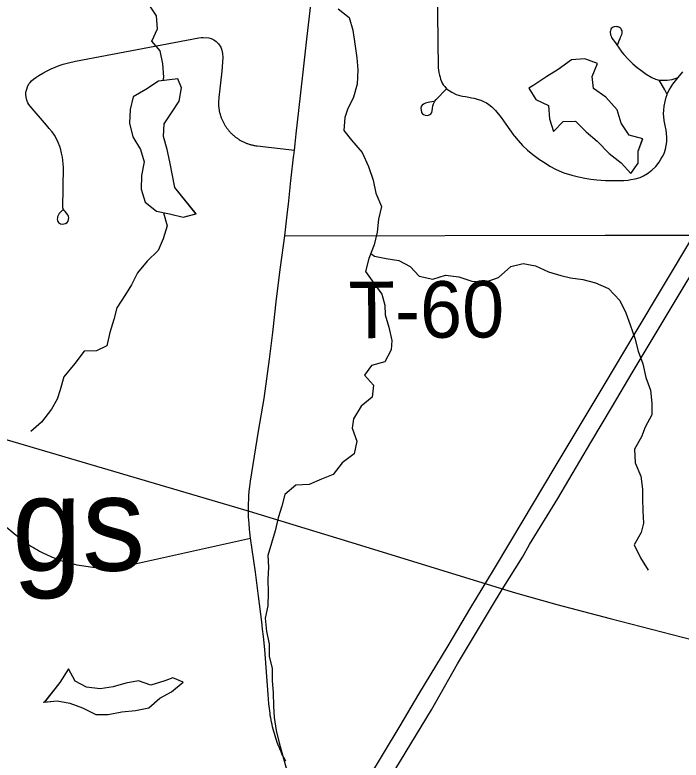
# Model space of a CAD drawing. Extents: x 0 to 34, y 0 to 22.
# Drawn here: x 5.8802 to 6.2147, y 14.8603 to 15.2346 of the extents above; entities that cross this region are included whole.
import ezdxf

# ---------------------------------------------------------------- set-up
doc = ezdxf.new("R2010")
doc.units = 0
for name, color, linetype in [('GM_X_County_Road', 7, 'Continuous'), ('GM_X_Interstate_Route', 7, 'Continuous'), ('GM_X_Major_River', 7, 'Continuous'), ('GM_X_Minor_Lake', 7, 'Continuous'), ('GM_X_Minor_Lake_Text', 7, 'Continuous'), ('GM_X_Minor_River', 7, 'Continuous'), ('GM_X_Rail_Line', 7, 'Continuous'), ('GM_X_Township_Road', 7, 'Continuous'), ('GM_X_Township_Road_Text', 7, 'Continuous')]:
    doc.layers.add(name, color=color, linetype=linetype)

msp = doc.modelspace()

# ---------------------------------------------------------------- linework, layer by layer
at = {"layer": 'GM_X_County_Road'}
for points in [[(6.01571, 15.1237), (6.01705, 15.13566), (6.01748, 15.13958), (6.01841, 15.14791), (6.01863, 15.14993), (6.01879, 15.1513), (6.01896, 15.15282), (6.0201, 15.16312), (6.02019, 15.16395), (6.0205, 15.16667), (6.02086, 15.16976), (6.02146, 15.17481), (6.02274, 15.18654), (6.0249, 15.20591), (6.02676, 15.22248), (6.02956, 15.24694)], [(6.01616, 14.85978), (6.01566, 14.86071), (6.01518, 14.86164), (6.01471, 14.86258), (6.01426, 14.86353), (6.01382, 14.86448), (6.0134, 14.86545), (6.013, 14.86642), (6.01262, 14.8674), (6.01225, 14.86838), (6.01194, 14.86917), (6.01154, 14.87028), (6.01116, 14.87138), (6.0108, 14.8725), (6.01045, 14.87362), (6.01013, 14.87474), (6.00983, 14.87587), (6.00955, 14.87701), (6.00928, 14.87815), (6.00904, 14.8793), (6.00882, 14.88045), (6.00861, 14.8816), (6.00843, 14.88276), (6.00827, 14.88392), (6.00768, 14.88863), (6.0073, 14.89326), (6.00571, 14.91589), (6.00495, 14.92242), (6.00457, 14.92614), (6.00411, 14.92978), (6.00252, 14.94269), (6.00107, 14.95461), (5.99856, 14.97179), (5.99805, 14.97629), (5.99777, 14.97919), (5.99754, 14.98244), (5.99742, 14.98591), (5.99748, 14.98899), (5.99757, 14.99133), (5.99766, 14.9932), (5.99788, 14.99543), (5.99811, 14.99764), (5.9985, 15.00044), (6.00249, 15.02549), (6.00529, 15.04195), (6.00801, 15.06166), (6.00961, 15.0751), (6.0116, 15.0919), (6.01354, 15.10796), (6.01571, 15.1237)]]:
    msp.add_lwpolyline(points, dxfattribs=at)
at = {"layer": 'GM_X_Interstate_Route'}
for points in [[(6.05073, 14.82195), (6.0893, 14.88549), (6.1024, 14.90857), (6.11951, 14.93717), (6.12489, 14.946), (6.13497, 14.96219), (6.13857, 14.96865), (6.15271, 14.99176), (6.1693, 15.01983), (6.18018, 15.03807), (6.19015, 15.05477), (6.21115, 15.09005), (6.22504, 15.11311), (6.23148, 15.12396), (6.23191, 15.12468), (6.23947, 15.1371), (6.24705, 15.14972), (6.2552, 15.16337), (6.26428, 15.1786), (6.27322, 15.19343)], [(6.05745, 14.85063), (6.07367, 14.87749), (6.08305, 14.89341), (6.0977, 14.91765), (6.10917, 14.93701), (6.12046, 14.95572), (6.12918, 14.97032), (6.15146, 15.00757), (6.17657, 15.04943), (6.19105, 15.07385), (6.22109, 15.12395), (6.23657, 15.14977), (6.26407, 15.19558)]]:
    msp.add_lwpolyline(points, dxfattribs=at)
at = {"layer": 'GM_X_Major_River'}
msp.add_lwpolyline([(6.04248, 15.23763), (6.04799, 15.2333), (6.04991, 15.22686), (6.05088, 15.22004), (6.05186, 15.21303), (6.05245, 15.20696), (6.0521, 15.19976), (6.05024, 15.1933), (6.04723, 15.18703), (6.04592, 15.18305), (6.04538, 15.1766), (6.04919, 15.17169), (6.05451, 15.16545), (6.05776, 15.15845), (6.06006, 15.15164), (6.06141, 15.14501), (6.06428, 15.13839), (6.06279, 15.13193), (6.06206, 15.12548), (6.06057, 15.11903), (6.05795, 15.11219), (6.05627, 15.10574), (6.06046, 15.09988), (6.06446, 15.0944), (6.066, 15.08872), (6.06602, 15.08398), (6.06794, 15.07773), (6.06948, 15.0711), (6.06912, 15.06636), (6.06593, 15.06028), (6.05931, 15.05855), (6.05573, 15.0536), (6.06029, 15.04869), (6.05956, 15.04262), (6.05409, 15.03805), (6.05014, 15.03177), (6.04959, 15.02703), (6.05189, 15.02041), (6.05059, 15.01414), (6.04455, 15.00957), (6.04003, 15.00367), (6.03417, 15.00137), (6.02794, 14.99869), (6.02131, 14.99847), (6.01565, 14.9937), (6.01416, 14.98782), (6.01229, 14.98193), (6.0108, 14.97548), (6.00894, 14.96921), (6.00726, 14.96314), (6.00747, 14.95726), (6.00712, 14.95101), (6.00733, 14.94437), (6.00717, 14.93773), (6.00587, 14.93166), (6.00647, 14.92484), (6.00782, 14.91878), (6.00784, 14.91252), (6.00938, 14.90627), (6.00941, 14.90021), (6.00981, 14.89414), (6.01003, 14.88732), (6.01043, 14.88163), (6.0114, 14.87519), (6.01295, 14.86894), (6.01468, 14.86231), (6.0166, 14.85568)], dxfattribs=at)
at = {"layer": 'GM_X_Minor_Lake'}
for points in [[(6.19543, 15.17234), (6.18866, 15.17425), (6.18457, 15.18025), (6.18255, 15.18685), (6.17693, 15.19319), (6.17078, 15.19763), (6.1701, 15.20369), (6.17263, 15.21019), (6.16633, 15.21254), (6.1597, 15.21203), (6.15297, 15.20716), (6.14734, 15.20364), (6.14078, 15.19935), (6.1382, 15.19772)], [(6.1954, 15.17235), (6.18866, 15.17425), (6.18457, 15.18025), (6.18255, 15.18685), (6.17693, 15.19319), (6.17078, 15.19763), (6.1701, 15.20369), (6.17263, 15.21019), (6.16633, 15.21254), (6.1597, 15.21203), (6.15297, 15.20716), (6.14734, 15.20364), (6.14078, 15.19935), (6.13826, 15.19776)], [(5.95234, 15.20135), (5.94586, 15.1972), (5.93948, 15.19348), (5.93808, 15.187), (5.93764, 15.18016), (5.93947, 15.17336), (5.9432, 15.16698), (5.94502, 15.16076), (5.94382, 15.1539), (5.94357, 15.14707), (5.94559, 15.14046), (5.95136, 15.13602), (5.95783, 15.13462), (5.96469, 15.13304), (5.9711, 15.13459)], [(5.95233, 15.20134), (5.94586, 15.1972), (5.93948, 15.19348), (5.93808, 15.187), (5.93764, 15.18016), (5.93947, 15.17336), (5.9432, 15.16698), (5.94502, 15.16076), (5.94382, 15.1539), (5.94357, 15.14707), (5.94559, 15.14046), (5.95136, 15.13602), (5.95783, 15.13462), (5.96469, 15.13304), (5.97114, 15.1346)], [(5.97114, 15.1346), (5.96043, 15.14795), (5.95791, 15.16081), (5.95666, 15.16705), (5.95483, 15.17346), (5.95509, 15.17992), (5.95915, 15.18588), (5.96266, 15.19126), (5.96386, 15.19792), (5.96205, 15.20249), (5.95233, 15.20134)], [(5.97116, 15.13458), (5.96043, 15.14795), (5.95791, 15.16081), (5.95666, 15.16705), (5.95483, 15.17346), (5.95509, 15.17992), (5.95915, 15.18588), (5.96266, 15.19126), (5.96386, 15.19792), (5.96205, 15.20249), (5.95235, 15.20135)], [(6.13816, 15.19778), (6.14168, 15.19215), (6.14818, 15.18905), (6.14868, 15.18242), (6.1507, 15.176), (6.15554, 15.18103), (6.16161, 15.18114), (6.16701, 15.17593), (6.1726, 15.1711), (6.1786, 15.16495), (6.18456, 15.16032), (6.1894, 15.15491), (6.1931, 15.1601), (6.19318, 15.16618), (6.19534, 15.1721)], [(6.1382, 15.19772), (6.14168, 15.19215), (6.14818, 15.18905), (6.14868, 15.18242), (6.1507, 15.176), (6.15554, 15.18103), (6.16161, 15.18114), (6.16701, 15.17593), (6.1726, 15.1711), (6.1786, 15.16495), (6.18456, 15.16032), (6.1894, 15.15491), (6.1931, 15.1601), (6.19318, 15.16618), (6.19543, 15.17234)], [(5.95952, 14.90165), (5.95538, 14.90005), (5.9484, 14.89802), (5.94229, 14.90019), (5.93587, 14.89893), (5.92945, 14.8971), (5.92302, 14.89603), (5.91618, 14.89685), (5.91043, 14.89997), (5.90709, 14.90617), (5.90267, 14.89925), (5.89496, 14.88948)], [(5.95952, 14.90165), (5.95538, 14.90005), (5.9484, 14.89802), (5.94229, 14.90019), (5.93587, 14.89893), (5.92945, 14.8971), (5.92302, 14.89603), (5.91618, 14.89685), (5.91043, 14.89997), (5.90709, 14.90617), (5.90267, 14.89925), (5.89502, 14.88956)], [(5.89432, 14.88942), (5.90132, 14.89012), (5.90779, 14.88891), (5.9141, 14.88656), (5.9208, 14.88327), (5.92706, 14.8832), (5.93386, 14.88447), (5.94067, 14.88517), (5.94747, 14.88662), (5.95288, 14.89147), (5.95889, 14.89462), (5.96468, 14.89947), (5.95952, 14.90165)], [(5.89496, 14.88948), (5.90132, 14.89012), (5.90779, 14.88891), (5.9141, 14.88656), (5.9208, 14.88327), (5.92706, 14.8832), (5.93386, 14.88447), (5.94067, 14.88517), (5.94747, 14.88662), (5.95288, 14.89147), (5.95889, 14.89462), (5.96468, 14.89947), (5.95952, 14.90165)]]:
    msp.add_lwpolyline(points, dxfattribs=at)
at = {"layer": 'GM_X_Minor_River'}
for points in [[(5.95466, 15.20165), (5.95504, 15.20326), (5.95453, 15.21008), (5.95308, 15.2165), (5.94901, 15.22136), (5.95174, 15.22767), (5.95124, 15.23411), (5.94733, 15.24011), (5.946, 15.24831)], [(5.95478, 15.13528), (5.95484, 15.13512), (5.95662, 15.12872), (5.95465, 15.12204), (5.95211, 15.1163), (5.94652, 15.11088), (5.94169, 15.1051), (5.93877, 15.09897), (5.93564, 15.09417), (5.9314, 15.08745), (5.92981, 15.08154), (5.92784, 15.07505), (5.92626, 15.06838), (5.92119, 15.06581), (5.91493, 15.0657), (5.9103, 15.05954), (5.90474, 15.05279), (5.90296, 15.04631), (5.90134, 15.04153), (5.89859, 15.03655), (5.89359, 15.03), (5.88818, 15.02535)], [(6.05895, 15.1148), (6.06079, 15.11334), (6.06666, 15.11223), (6.07291, 15.11131), (6.0786, 15.1083), (6.08317, 15.10339), (6.08999, 15.10191), (6.09642, 15.10383), (6.10305, 15.1031), (6.10968, 15.10086), (6.11631, 15.10032), (6.12293, 15.10262), (6.12915, 15.10815), (6.13539, 15.10969), (6.14164, 15.10858), (6.14809, 15.10558), (6.15435, 15.10371), (6.15909, 15.10259), (6.16534, 15.10167), (6.17178, 15.1), (6.17823, 15.09718), (6.18393, 15.09114), (6.18699, 15.08489), (6.1891, 15.07884), (6.19139, 15.07221), (6.19312, 15.06577), (6.19542, 15.05934), (6.19696, 15.05252), (6.19926, 15.04608), (6.20005, 15.03964), (6.20007, 15.03376), (6.19669, 15.02749), (6.19481, 15.02274), (6.19124, 15.01647), (6.19165, 15.00965), (6.19452, 15.00284), (6.1953, 14.99639), (6.19532, 14.99165), (6.19554, 14.9854), (6.19575, 14.97933), (6.19463, 14.97459), (6.19106, 14.9685), (6.19431, 14.96188), (6.19812, 14.95564)]]:
    msp.add_lwpolyline(points, dxfattribs=at)
at = {"layer": 'GM_X_Rail_Line'}
msp.add_lwpolyline([(5.58039, 15.05671), (5.71061, 15.04823), (5.7356, 15.04666), (5.75087, 15.0456), (5.76651, 15.04413), (5.77394, 15.04337), (5.7884, 15.04135), (5.8057, 15.03872), (5.82006, 15.03579), (5.83544, 15.03235), (5.85294, 15.028), (5.99778, 14.98531), (6.04775, 14.97004), (6.08852, 14.9576), (6.13029, 14.94465), (6.15224, 14.93848), (6.17915, 14.9314), (6.22569, 14.91944)], dxfattribs=at)
at = {"layer": 'GM_X_Township_Road'}
for points in [[(6.09194, 15.27583), (6.09278, 15.20807), (6.0929, 15.20675), (6.09304, 15.20563), (6.09333, 15.20428), (6.09363, 15.20325), (6.09396, 15.20226), (6.09436, 15.20114), (6.09475, 15.20028), (6.09528, 15.19949), (6.09601, 15.19857), (6.09693, 15.19751), (6.0995, 15.1958), (6.10168, 15.19468), (6.10293, 15.19428), (6.10405, 15.19395), (6.10497, 15.19378), (6.10636, 15.19356), (6.10811, 15.19325), (6.10949, 15.193), (6.11075, 15.19276), (6.11236, 15.19235), (6.11419, 15.19171), (6.11545, 15.19111), (6.11697, 15.19038), (6.1181, 15.18963), (6.11958, 15.18845), (6.12156, 15.18652), (6.12438, 15.18305), (6.12671, 15.17969), (6.12869, 15.17682), (6.13076, 15.17405)], [(6.18278, 15.21938), (6.18319, 15.22065), (6.18364, 15.22175), (6.18401, 15.22257), (6.18433, 15.22337), (6.18463, 15.22409), (6.18486, 15.22481), (6.18503, 15.22548), (6.18509, 15.22617), (6.18503, 15.22666), (6.18483, 15.22712), (6.18453, 15.22755), (6.1842, 15.22792), (6.18377, 15.22821), (6.18301, 15.22854), (6.18255, 15.22864), (6.18203, 15.2287), (6.18104, 15.22857), (6.18054, 15.22841), (6.18008, 15.22811), (6.17962, 15.22768), (6.17936, 15.22719), (6.17919, 15.22659), (6.17913, 15.2261), (6.17926, 15.22452), (6.17952, 15.22383), (6.17982, 15.22317), (6.18048, 15.22218), (6.18124, 15.22115), (6.18209, 15.22007), (6.18275, 15.21911), (6.18327, 15.21842), (6.18374, 15.21763), (6.18422, 15.21683), (6.18488, 15.21595), (6.18597, 15.21466), (6.18822, 15.21226), (6.19047, 15.21006), (6.1926, 15.20823), (6.19442, 15.20678), (6.1971, 15.20481), (6.19998, 15.20317), (6.2019, 15.20235), (6.20371, 15.20181), (6.2054, 15.20177), (6.20762, 15.20188), (6.21012, 15.20221), (6.21324, 15.20308)], [(5.9043, 15.13676), (5.90249, 15.13483), (5.90187, 15.13388), (5.90162, 15.1332), (5.9015, 15.13259), (5.90144, 15.13198), (5.90156, 15.1313), (5.90175, 15.13075), (5.90211, 15.13026), (5.90304, 15.1297), (5.90384, 15.12952), (5.90469, 15.12958), (5.90555, 15.12983), (5.90647, 15.13038), (5.9069, 15.13106), (5.90715, 15.13179), (5.90727, 15.13259), (5.90715, 15.13339), (5.90678, 15.13418), (5.90617, 15.13498), (5.90538, 15.13585), (5.90488, 15.13627), (5.90451, 15.13683), (5.90433, 15.13762), (5.9045, 15.15819), (5.90426, 15.1615), (5.904, 15.16319), (5.90363, 15.16513), (5.90325, 15.16682), (5.90275, 15.1685), (5.90194, 15.1705), (5.90094, 15.17263), (5.9, 15.17426), (5.89882, 15.17594), (5.89744, 15.17758), (5.896, 15.17926), (5.88781, 15.18882), (5.88725, 15.18957), (5.88675, 15.19045), (5.88619, 15.19175), (5.88581, 15.19332), (5.88563, 15.1947), (5.8857, 15.19538), (5.88588, 15.19626), (5.88615, 15.19737), (5.88656, 15.19851), (5.88725, 15.19995), (5.88777, 15.20063), (5.8885, 15.20145), (5.88956, 15.20232), (5.89069, 15.20313), (5.89219, 15.2042), (5.89425, 15.20539), (5.89638, 15.20651), (5.89844, 15.20745), (5.90044, 15.20839), (5.90244, 15.2092), (5.90436, 15.20982), (5.90713, 15.21058), (5.91057, 15.21139), (5.97257, 15.22305), (5.97377, 15.2232), (5.97464, 15.22325), (5.97755, 15.2231), (5.97877, 15.2227), (5.98002, 15.22208), (5.98121, 15.22127), (5.98245, 15.22008), (5.98352, 15.21845), (5.98408, 15.21695), (5.98439, 15.21526), (5.98452, 15.2132), (5.98402, 15.20626), (5.98252, 15.19307), (5.98239, 15.1907), (5.98245, 15.18888), (5.98257, 15.18781), (5.98262, 15.18743), (5.98268, 15.18705), (5.98275, 15.18667), (5.98282, 15.18629), (5.9829, 15.18592), (5.98299, 15.18554), (5.98308, 15.18517), (5.98318, 15.1848), (5.98328, 15.18443), (5.98339, 15.18407), (5.98351, 15.1837), (5.98364, 15.18333), (5.98377, 15.18297), (5.98391, 15.18262), (5.98405, 15.18226), (5.9842, 15.18191), (5.98435, 15.18156), (5.98451, 15.18121), (5.98468, 15.18087), (5.98486, 15.18052), (5.98504, 15.18018), (5.98522, 15.17985), (5.98541, 15.17951), (5.98561, 15.17918), (5.98581, 15.17886), (5.98602, 15.17854), (5.98624, 15.17822), (5.98646, 15.1779), (5.98668, 15.17759), (5.98691, 15.17729), (5.98715, 15.17698), (5.98739, 15.17669), (5.98764, 15.17639), (5.98789, 15.1761), (5.98814, 15.17582), (5.9884, 15.17553), (5.98867, 15.17526), (5.98894, 15.17499), (5.98922, 15.17472), (5.9895, 15.17446), (5.98978, 15.1742), (5.99007, 15.17395), (5.99037, 15.1737), (5.99067, 15.17346), (5.99097, 15.17323), (5.99127, 15.17299), (5.99158, 15.17277), (5.9919, 15.17254), (5.99222, 15.17233), (5.99254, 15.17212), (5.99286, 15.17192), (5.99319, 15.17172), (5.99352, 15.17153), (5.99386, 15.17134), (5.9942, 15.17116), (5.99454, 15.17099), (5.99489, 15.17082), (5.99523, 15.17066), (5.99558, 15.1705), (5.99594, 15.17035), (5.99629, 15.17021), (5.99665, 15.17007), (5.99701, 15.16994), (5.99737, 15.16981), (5.99774, 15.16969), (5.9981, 15.16958), (5.99847, 15.16947), (5.99884, 15.16937), (5.99922, 15.16928), (5.99959, 15.16919), (5.99996, 15.16911), (6.00034, 15.16904), (6.00072, 15.16897), (6.0011, 15.16891), (6.00148, 15.16886), (6.00186, 15.16881), (6.0205, 15.16667)], [(6.21324, 15.20308), (6.2156, 15.20596)], [(6.13076, 15.17405), (6.13106, 15.17365), (6.13284, 15.17148), (6.13512, 15.16905), (6.13764, 15.16668), (6.14031, 15.1644), (6.14358, 15.16198), (6.14657, 15.16009), (6.14882, 15.15867), (6.15154, 15.15718), (6.15345, 15.15631), (6.15584, 15.1553), (6.15975, 15.15407), (6.16321, 15.15322), (6.16643, 15.15258), (6.1693, 15.15214), (6.17232, 15.15174), (6.17667, 15.15149), (6.18043, 15.15139), (6.1836, 15.15144), (6.18597, 15.15149), (6.18805, 15.15164), (6.18948, 15.15184), (6.19166, 15.15229), (6.19408, 15.15298), (6.19576, 15.15372), (6.19784, 15.15491), (6.20007, 15.15659), (6.20203, 15.15843), (6.20363, 15.1606), (6.20456, 15.16207), (6.20536, 15.16346), (6.2061, 15.165), (6.2068, 15.16712), (6.20724, 15.16901), (6.20754, 15.17089), (6.20759, 15.17301), (6.20739, 15.17519), (6.20714, 15.17672), (6.20675, 15.179), (6.20625, 15.18162), (6.20605, 15.18335), (6.20591, 15.18493), (6.206, 15.18667), (6.20625, 15.18874), (6.20665, 15.19107), (6.20714, 15.19324), (6.20764, 15.19464), (6.20786, 15.19525), (6.20882, 15.19712), (6.2105, 15.19976), (6.21324, 15.20308)], [(6.20764, 15.19464), (6.20644, 15.19695), (6.20469, 15.20015), (6.20371, 15.20181)], [(6.09053, 15.19105), (6.08757, 15.19052), (6.08631, 15.1902), (6.08528, 15.18976), (6.08462, 15.18929), (6.08414, 15.18861), (6.08394, 15.18775), (6.08427, 15.18551), (6.08479, 15.18485), (6.08532, 15.18459), (6.08625, 15.18419), (6.08711, 15.18412), (6.0879, 15.1842), (6.08858, 15.1845), (6.08908, 15.18498), (6.08948, 15.18564), (6.08968, 15.18643), (6.08987, 15.18763), (6.09007, 15.18887), (6.09033, 15.18993), (6.091, 15.19118), (6.09172, 15.19211), (6.09693, 15.19751)], [(6.01571, 15.1237), (6.17655, 15.12389), (6.22109, 15.12395), (6.23148, 15.12396), (6.23336, 15.12396), (6.3484, 15.12434), (6.3666, 15.12441), (6.37405, 15.1245), (6.37758, 15.12455), (6.38508, 15.12448), (6.39223, 15.12452), (6.39592, 15.12454), (6.42166, 15.12459), (6.4401, 15.12482), (6.45651, 15.12499), (6.50082, 15.1255), (6.51898, 15.12574), (6.53451, 15.12587), (6.56367, 15.12613), (6.6058, 15.1265), (6.73242, 15.12662), (6.74086, 15.12664)], [(5.86219, 14.98849), (5.88269, 14.97175), (5.88362, 14.97102), (5.88456, 14.97032), (5.88551, 14.96963), (5.88648, 14.96895), (5.88746, 14.9683), (5.88845, 14.96766), (5.88945, 14.96704), (5.89046, 14.96643), (5.89148, 14.96585), (5.89251, 14.96528), (5.89356, 14.96473), (5.89461, 14.9642), (5.89566, 14.96368), (5.89673, 14.96319), (5.89781, 14.96271), (5.89889, 14.96225), (5.89998, 14.96181), (5.90108, 14.96139), (5.90219, 14.96099), (5.9033, 14.96061), (5.90442, 14.96024), (5.90555, 14.9599), (5.90668, 14.95957), (5.90781, 14.95927), (5.90895, 14.95898), (5.9101, 14.95871), (5.91125, 14.95846), (5.9124, 14.95823), (5.91356, 14.95802), (5.91472, 14.95783), (5.91588, 14.95767), (5.91704, 14.95752), (5.91821, 14.95739), (5.91938, 14.95728), (5.92055, 14.95719), (5.92172, 14.95712), (5.92289, 14.95708), (5.92876, 14.95715), (5.92992, 14.95722), (5.93109, 14.95732), (5.93226, 14.95743), (5.93342, 14.95757), (5.93458, 14.95773), (5.93574, 14.95791), (5.9369, 14.9581), (5.93805, 14.95832), (5.93977, 14.95868), (5.99856, 14.97179)]]:
    msp.add_lwpolyline(points, dxfattribs=at)

# ---------------------------------------------------------------- texts
at = {"layer": 'GM_X_Minor_Lake_Text'}
msp.add_text('Demings ', height=0.047368, rotation=0.366, dxfattribs=at).set_placement((5.69576, 14.95397))
at = {"layer": 'GM_X_Township_Road_Text'}
msp.add_text('T-60', height=0.028409, rotation=0.3533, dxfattribs=at).set_placement((6.04783, 15.07215))

doc.saveas('drawing.dxf')
